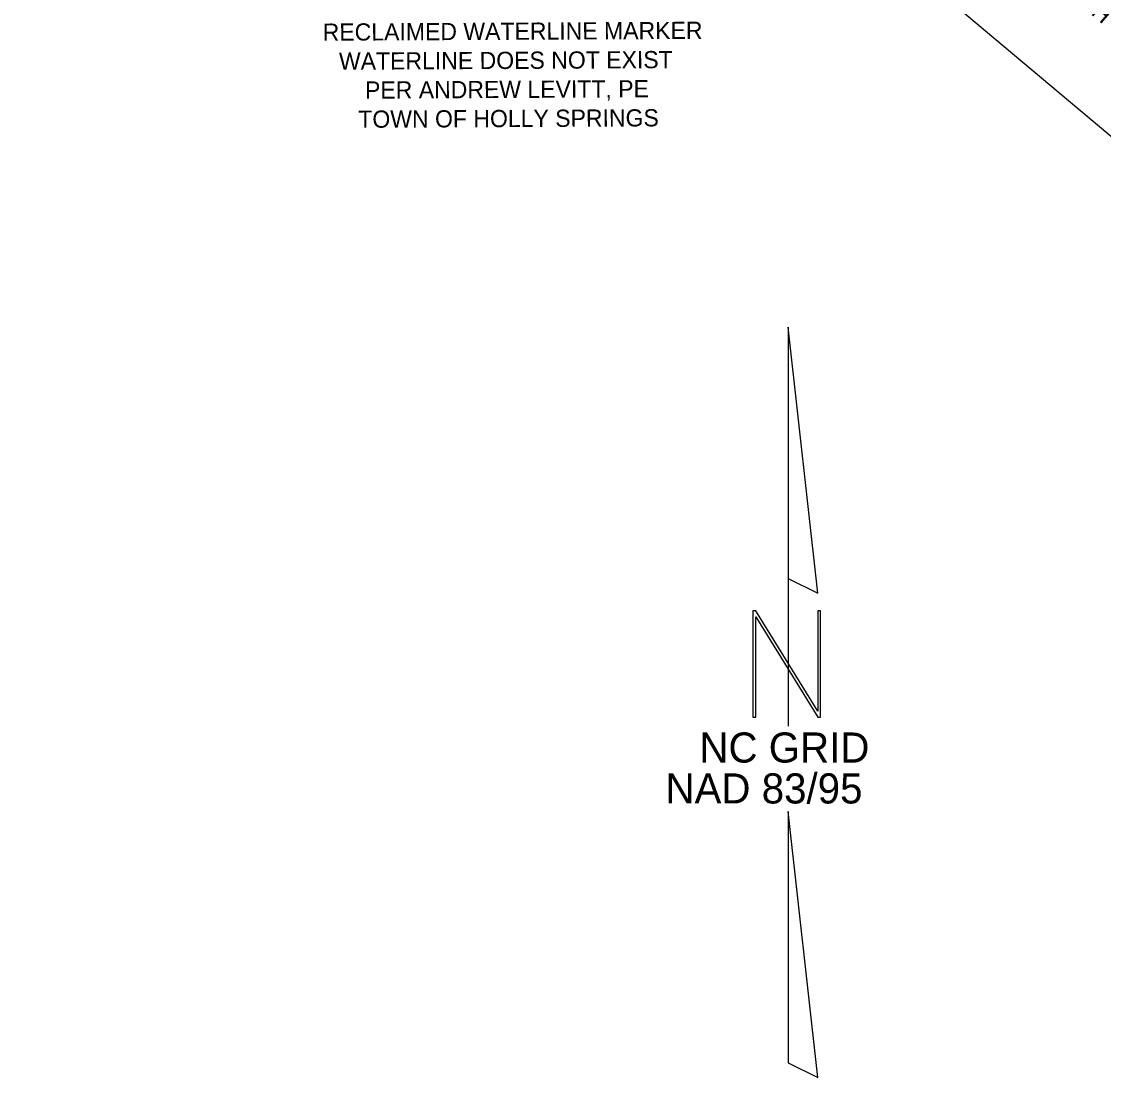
# Model space of a CAD drawing. Extents: x 2057786 to 2059508, y 687766 to 689280.
# Drawn here: x 2058243.9 to 2058495.3, y 688565.4 to 688810.6 of the extents above; entities that cross this region are included whole.
import ezdxf

# ---------------------------------------------------------------- set-up
doc = ezdxf.new("R2010")
doc.units = 0
for name, color, linetype in [('CTL North Arrow NAD 83 95 CELL', 7, 'Continuous'), ('Exist Roads EOP', 7, 'Continuous'), ('Exist Utilities Water Valve Text', 7, 'Continuous'), ('Old_Level_28', 7, 'Continuous'), ('Old_Level_8', 7, 'Continuous')]:
    doc.layers.add(name, color=color, linetype=linetype)

# ---------------------------------------------------------------- blocks, each defined once
blk = doc.blocks.new('CTL NORTH ARROW NAD 83 95')
at = {"layer": 'CTL North Arrow NAD 83 95 CELL'}
for points in [[(-0.003, 1.7458), (-0.003, 0.5793), (0.1345, 0.5105)], [(-0.1675, -0.0653), (-0.1537, -0.0653), (-0.1537, 0.4012), (0.1345, -0.0653), (0.1482, -0.0653), (0.1482, 0.4285), (0.1345, 0.4285), (0.1345, -0.038), (-0.1537, 0.4285), (-0.1675, 0.4285)], [(-0.003, -1.671), (0.1345, -1.7392), (-0.003, -0.5045)]]:
    blk.add_lwpolyline(points, close=True, dxfattribs=at)
blk.add_lwpolyline([(-0.003, 0.5793), (-0.003, -0.1067)], dxfattribs=at)
for s, p in [('NC GRID', (-0.4154, -0.2767)), ('NAD 83/95', (-0.5731, -0.4667))]:
    blk.add_text(s, height=0.14, dxfattribs=at).set_placement(p)

msp = doc.modelspace()

# ---------------------------------------------------------------- linework, layer by layer
at = {"layer": 'Exist Roads EOP'}
msp.add_spline([(2058790.44, 688783.33), (2058774.52, 688799.91), (2058750.56, 688821.57), (2058724.88, 688843.53), (2058697.06, 688865.63), (2058669.08, 688886.89), (2058642.64, 688905.34), (2058608.82, 688927.02), (2058574.14, 688948.51), (2058534.92, 688970.39), (2058490.85, 688994.7)], degree=3, dxfattribs=at)
at = {"layer": 'Old_Level_8'}
msp.add_lwpolyline([(2058243.89, 688914.56), (2058274.94, 688919.33), (2058297.8, 688918.3), (2058350.46, 688908.85), (2058379.27, 688886.03), (2058459.18, 688815.88), (2058518.04, 688766.49), (2058546.6, 688746.07), (2058577.46, 688734.39), (2058606.33, 688729.69), (2058618.83, 688725.97), (2058623.23, 688723.41), (2058623.36, 688718.56), (2058621.09, 688706.79), (2058622.32, 688699.87), (2058624.31, 688695.72), (2058627.84, 688693.91), (2058629.3, 688692.92), (2058633.15, 688691.6), (2058635.7, 688693.01)], dxfattribs=at)

# ---------------------------------------------------------------- block references
at = {"layer": 'CTL North Arrow NAD 83 95 CELL', "xscale": 50, "yscale": 50}
msp.add_blockref('CTL NORTH ARROW NAD 83 95', (2058422.17, 688652.35), dxfattribs=at)

# ---------------------------------------------------------------- texts
at = {"layer": 'Exist Utilities Water Valve Text'}
for s, p in [('RECLAIMED WATERLINE MARKER', (2058313.86, 688806.21)), ('WATERLINE DOES NOT EXIST', (2058317.64, 688799.47)), ('PER ANDREW LEVITT, PE', (2058323.7, 688792.75)), ('TOWN OF HOLLY SPRINGS', (2058322.14, 688785.98))]:
    msp.add_text(s, height=4, rotation=0.2769, dxfattribs=at).set_placement(p)
at = {"layer": 'Old_Level_28'}
for s, p in [('RIP-RAP SPILLWAY', (2058485.15, 688826.99)), ('(WIDTH VARIES)', (2058480.51, 688822.51))]:
    msp.add_text(s, height=4, rotation=319.3747, dxfattribs=at).set_placement(p)

doc.saveas('drawing.dxf')
